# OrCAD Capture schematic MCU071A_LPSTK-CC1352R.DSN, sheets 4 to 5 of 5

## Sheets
4 4_Battery: size A3
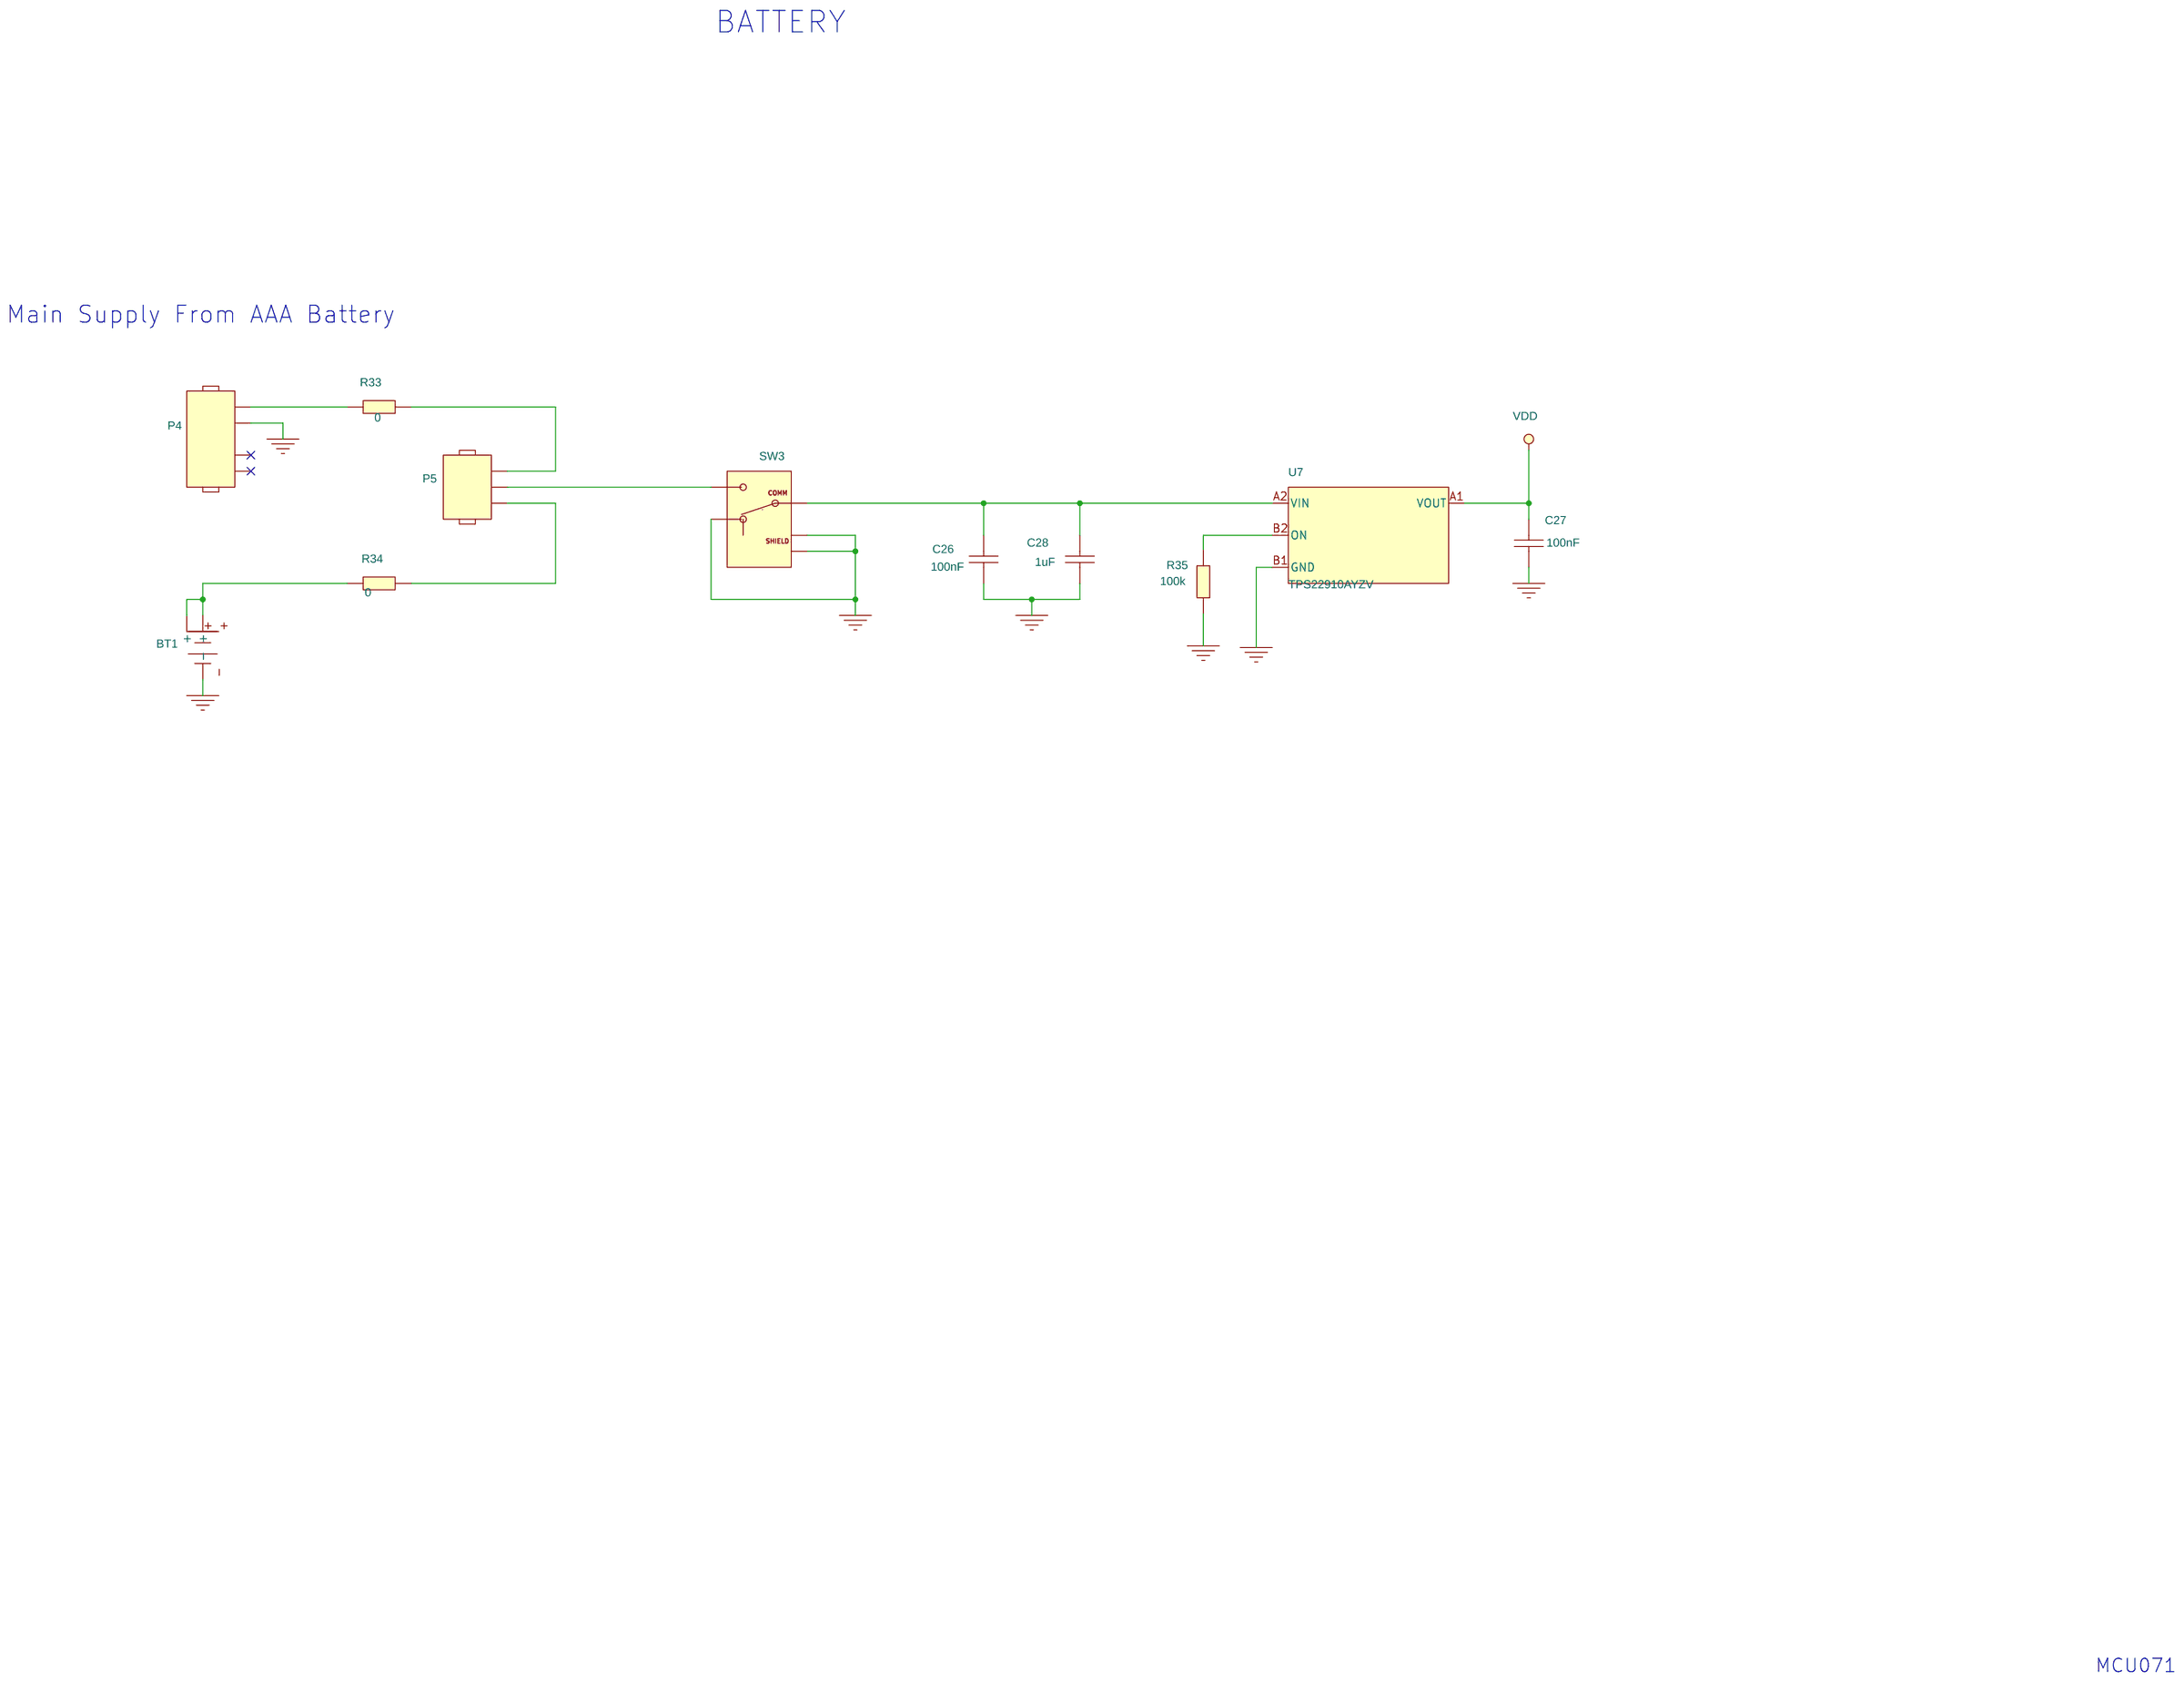
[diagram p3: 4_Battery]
5 5_Hardware: size A3
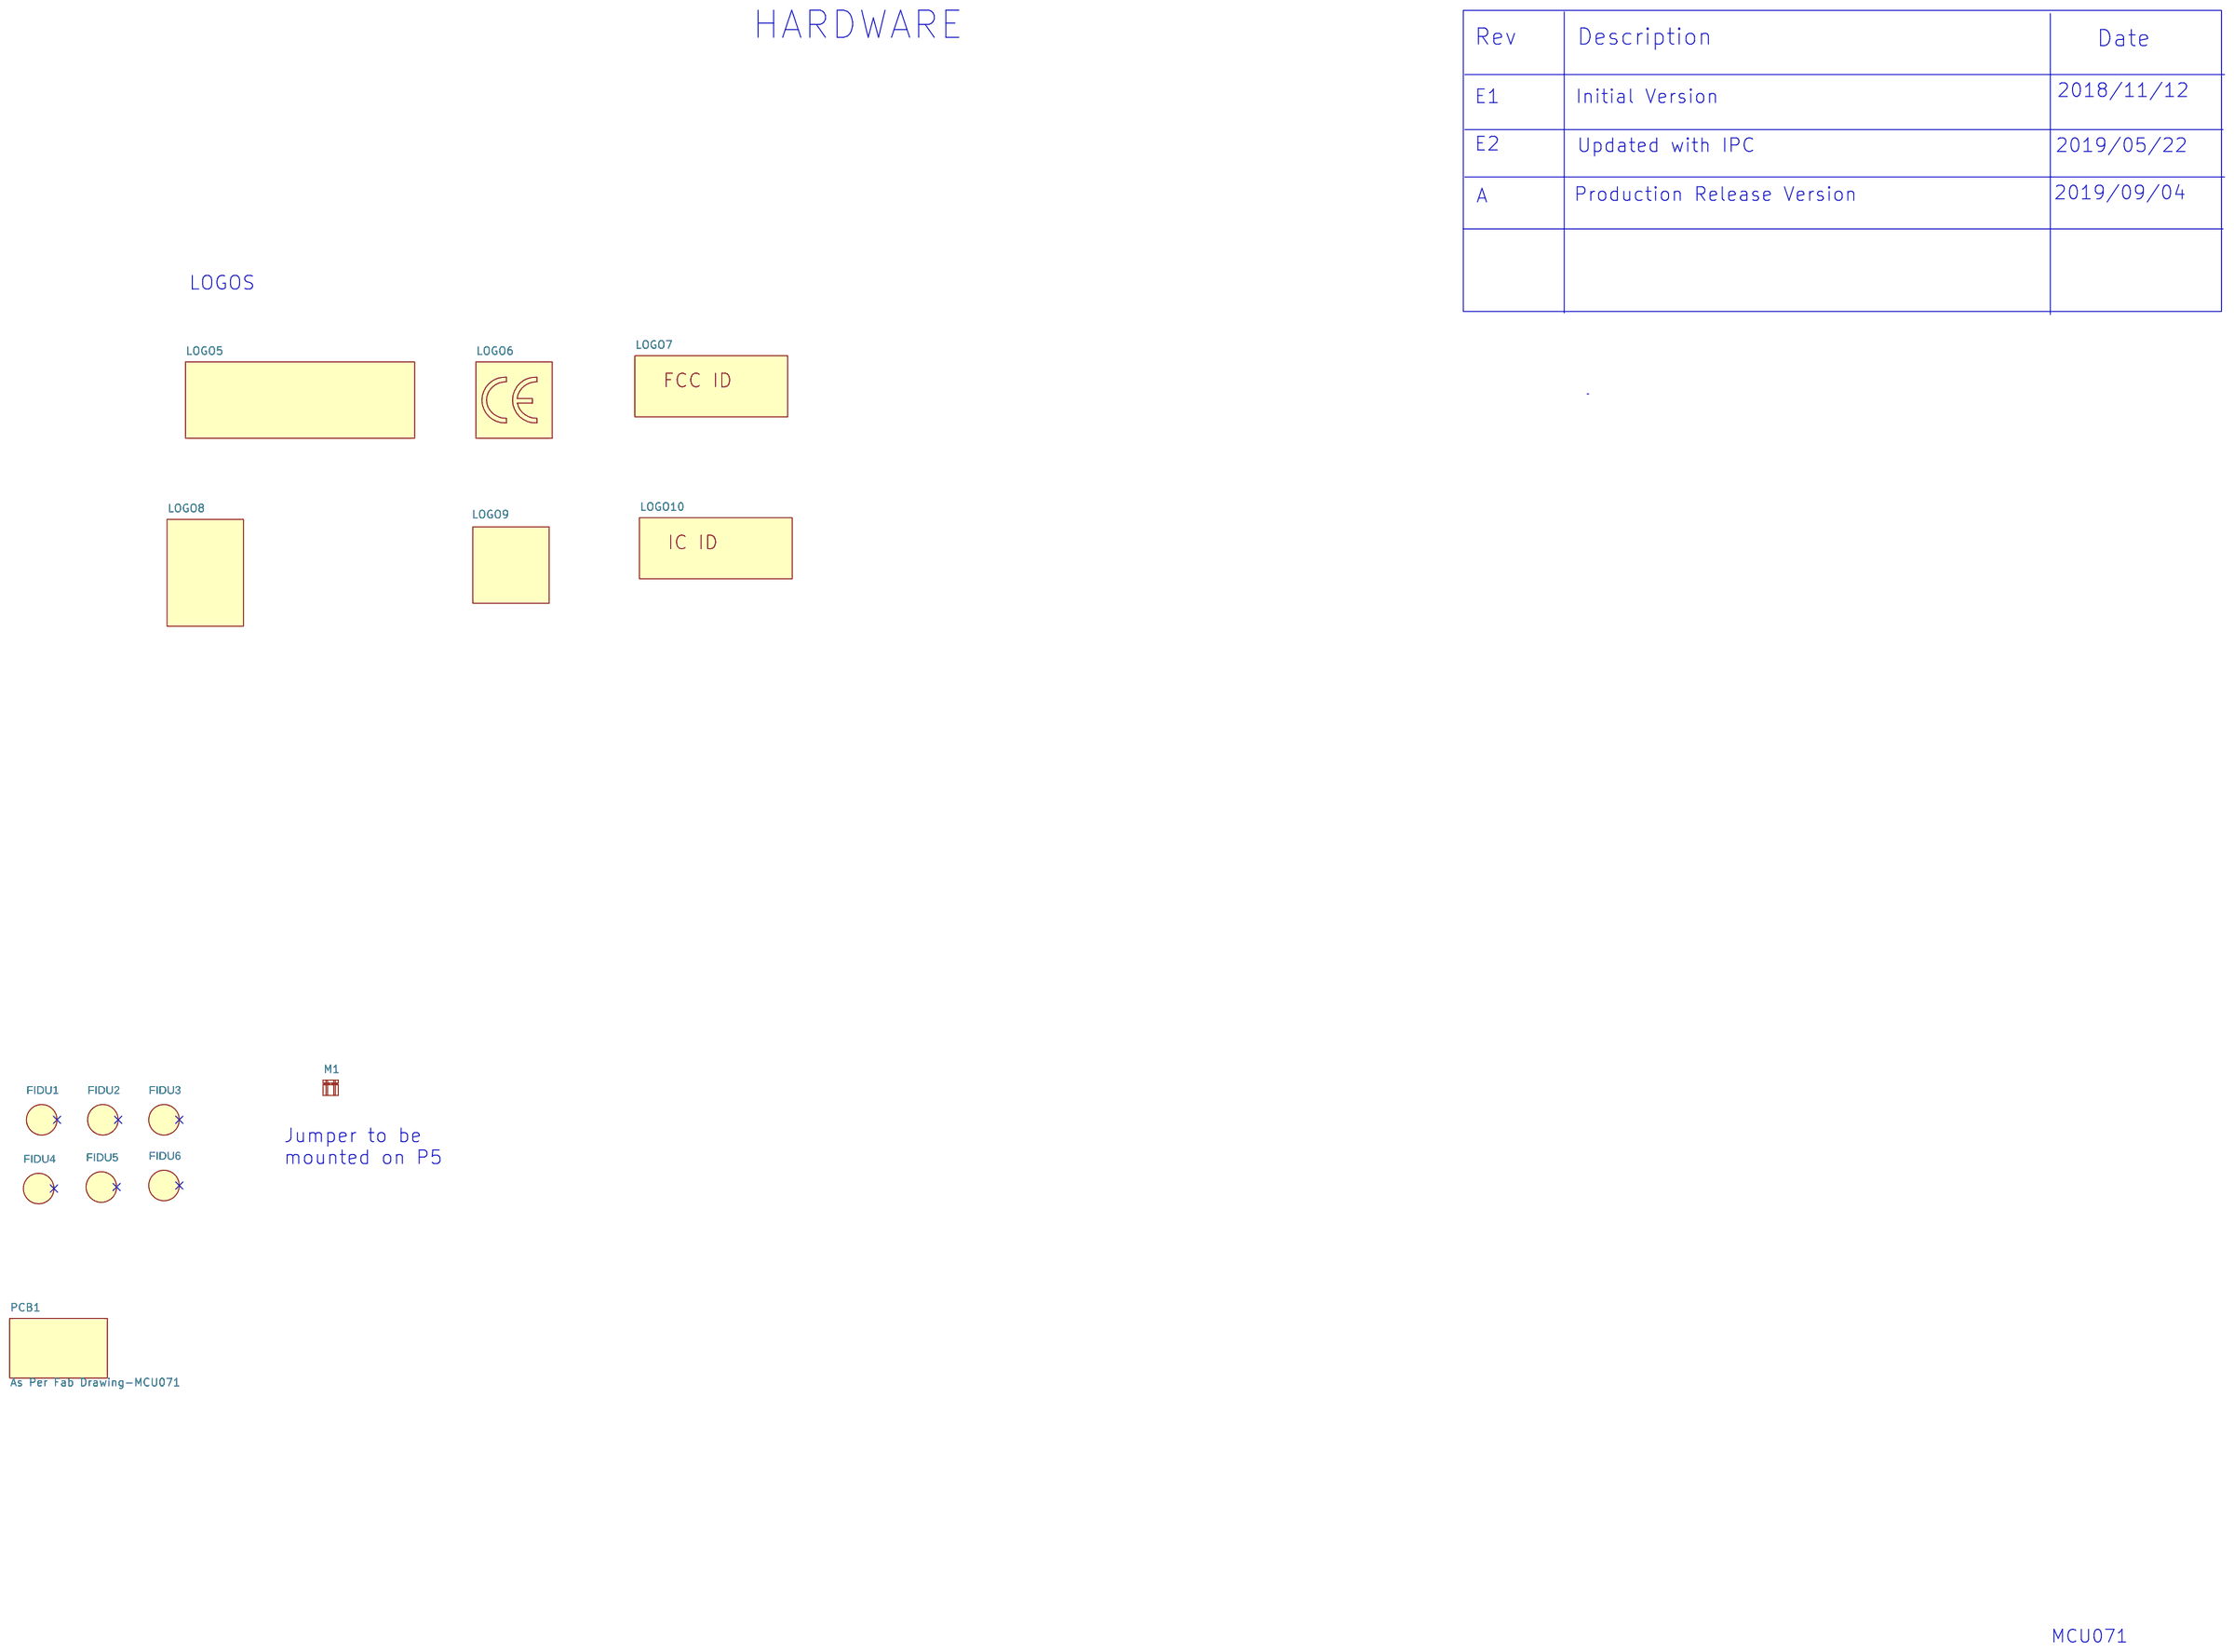
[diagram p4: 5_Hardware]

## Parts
sheet 4_Battery
BT1  BAT-HLD-001  [BAT_BATHLD001N]
C26  100nF  [CAPC1005X60A2N]
C27  100nF  [CAPC1005X60A2N]
C28  1uF  [CAPC1005X60A2N]
P4  CNT-1147H-02  [CNT_CNT1147H02_A2N]
P5  3220103S1210880  [HARWIN_M222010305_A2B]
R33  0  [RESC1005X40A2N]
R34  0  [RESC1005X40B2N]
R35  100k  [RESC0603X35B2N]
SW3  SH-12D01-VGX-H  [SW_SK12D01AVG_A2B]
U7  TPS22910AYZV  [BGAFC4C50P89X89X50]
sheet 5_Hardware
FIDU1  FIDU_1.27mm  [FID127X142]
FIDU2  FIDU_1.27mm  [FID127X142]
FIDU3  FIDU_1.27mm  [FID127X142]
FIDU4  FIDU_1.27mm  [FID127X142]
FIDU5  FIDU_1.27mm  [FID127X142]
FIDU6  FIDU_1.27mm  [FID127X142]
LOGO5  TI_LOGO  [TI_LOGO_1]
LOGO6  CE_Logo  [CE_MARKING]
LOGO7  FCC ID: Z64-LPSTK1352R  [LABEL_FOR_EVALUATION_ONLY]
LOGO8  TRASH_7mm  [TRASH_7MM]
LOGO9  ESD_Logo_5x5mm  [ESD_LABEL_5x5]
LOGO10  IC ID: 451I-LPSTKCC1352R  [LABEL_FOR_EVALUATION_ONLY]
M1  MJ-6B2.0X4.5  [SAMTEC_SNT100BKG]
PCB1  As Per Fab Drawing-MCU071  [TI_MCUxx]

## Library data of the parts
BT1 = BATT_3PINS: BATTERY, HOLDER, CR2032 AND CR2025 BATTERIES, SMD; ALT_SYMBOLS: BAT_BATHLD001L,BAT_BATHLD001M,BAT_BATHLD001AL,BAT_BATHLD001AM; Additional Datasheet URL: https://linxtechnologies.com/wp/wp-content/uploads/bat-hld-001.pdf; Budgetary Price: 0.2196 USD; Country of Origin: Missing Info; Datasheet URL: http://www.linxtechnologies.com/resources/documents/battery_holder_overview_guide.pdf; FPLIST: BAT_BATHLD001N,BAT_BATHLD001AN; Lead Time: 8; Mass: N/A; Maximum Operating Temperature: N/A; Minimum Operating Temperature: N/A; NOTEfied URL: https://notefied-dynamic-precision.com/NOTEfiedWebInterface/part/show?partNumber=10-00027; Packing Size: 100; Packing Type: Bulk; Part Number: 10-00027; Part Type: Battery|HOLDER; REACH/SVHC Compliance: Compliant; REACH/SVHC Details: SVHC List Version Jun 20, 2016; REACH/SVHC Source: REACH Declaration; REACH/SVHC Status: Unaffected; ROHS: Compliant; Revision: R013; Status: Released; Texas Part Status: Under Review; Type: Battery; Vendor: LINX; Vendor Part Status: Active
C26 C27 = CAPACITOR: CAPACITOR, CERAMIC X5R, 100nF, 10V, -10%+/10%, -55DEGC /+85DEGC, 0402, SMD; ALT_SYMBOLS: CAPC1005X60A2L,CAPC1005X60A2M; Additional Datasheet URL: http://www.avx.com/products/ceramic-capacitors/surface-mount/x5r-dielectric/; Budgetary Price: 0.004 EUR; Country of Origin: China,Czech Republic,El Salvador,Japan,Malaysia,United Kingdom; Datasheet URL: http://datasheets.avx.com/cx5r.pdf; Dielectric Type: X5R; Lead Time: 11; Mass: 0.001g; Maximum Operating Temperature: +85DEGC; Maximum Tolerance: +10%; Minimum Operating Temperature: -55DEGC; Minimum Tolerance: -10%; Mounting Type: SMD; NOTEfied URL: https://notefied-dynamic-precision.com/NOTEfiedWebInterface/part/show?partNumber=02-04065; PCB Package: 0402; Packing Size: 10000; Packing Type: Tape & Reel; Part Number: 02-04065; Part Type: Capacitor|CERAMIC|0402|STANDARD; ROHS: Compliant; Rated Voltage: 10V; Revision: R008; Status: Released; Type: Capacitor; Vendor: AVX; Vendor Part Number: 0402ZD104KAT2A; Vendor Part Status: Active
C28 = CAPACITOR: CAPACITOR, CERAMIC X5R, 1uF, 16V, -20%/+20%, -55DEGC/+85DEGC, 0402, SMD; ALT_SYMBOLS: CAPC1005X60A2L,CAPC1005X60A2M; Additional Datasheet URL: http://www.avx.com/products/ceramic-capacitors/surface-mount/x5r-dielectric/; Budgetary Price: 0.119 EUR; Country of Origin: United States; Datasheet URL: http://datasheets.avx.com/cx5r.pdf; Dielectric Type: X5R; Lead Time: 8; Mass: 0.001g; Maximum Operating Temperature: +85DEGC; Maximum Tolerance: +20%; Minimum Operating Temperature: -55DEGC; Minimum Tolerance: -20%; Mounting Type: SMD; NOTEfied URL: https://notefied-dynamic-precision.com/NOTEfiedWebInterface/part/show?partNumber=02-05023; PCB Package: 0402; Packing Size: 10000; Packing Type: Tape & Reel; Part Number: 02-05023; Part Type: Capacitor|CERAMIC|0402|STANDARD; ROHS: Compliant; Rated Voltage: 16V; Revision: R018; Status: Released; Type: Capacitor; Vendor: AVX; Vendor Part Number: 0402YD105MAT2A; Vendor Part Status: Active
P4 = CONN_HEADER_2_P_2MH_V1: CONNECTOR, HEADER, SHROUDED, MALE, RIGHT ANGLE, 1 ROW(S), 2 PINS, PITCH 1.25mm, SMD; ALT_SYMBOLS: CNT_CNT1147H02_A2L,CNT_CNT1147H02_A2M; Additional Datasheet URL: N/A; Datasheet URL: https://yccntcon.en.ec21.com/; Maximum Operating Temperature: +85DEGC; Minimum Operating Temperature: -40DEGC; Mounting Type: SMD; NOTEfied URL: https://notefied-dynamic-precision.com/NOTEfiedWebInterface/part/show?partNumber=06-07394; Number of Positions: 2; Number of Rows: 1; Packing Size: 2000; Packing Type: Tape & Reel; Part Number: 06-07394; Part Type: Connector|HEADER|SHROUDED; Pitch: 1.25mm; REACH/SVHC Compliance: Missing Info; REACH/SVHC Source: N/A; REACH/SVHC Status: Missing Info; ROHS: Compliant; Rated Current: 1A; Rated Voltage: 250V; Revision: R002; Status: Released; Texas Part Status: Under Review; Type: Connector; Vendor: CNT CONNECTORS; Vendor Part Status: Unconfirmed
P5 = CONN_HEADER_3_P_S: CONNECTOR, HEADER, MALE, STRAIGHT, 1 ROW, 3 PINS, PITCH 2mm, PTH; ALT_SYMBOLS: HARWIN_M222010305_A2A,HARWIN_M222010305_A2C; Additional Datasheet URL: https://cdn.harwin.com/pdfs/M22-201.pdf; Budgetary Price: 0.1066 USD; Country of Origin: Taiwan; Datasheet URL: https://cdn.harwin.com/pdfs/C018XX_M22_Series_Connectors.pdf; Mass: 0.071g; Maximum Operating Temperature: +105DEGC; Minimum Operating Temperature: -40DEGC; Mounting Type: PTH; NOTEfied URL: https://notefied-dynamic-precision.com/NOTEfiedWebInterface/part/show?partNumber=06-07362; Number of Positions: 3; Number of Rows: 1; Packing Size: 1000; Packing Type: Bulk; Part Number: 06-07362; Part Type: Connector|HEADER|STANDARD; Pitch: 2mm; REACH/SVHC Details: SVHC List Version; ROHS: Compliant; Rated Current: 2A; Rated Voltage: 650V; Revision: R003; Status: Released; Type: Connector; Vendor: LYCONN; Vendor Part Status: Active
R33 = RESISTOR: RESISTOR, THICK FILM, 0, 0.063W, 50V, -55DEGC/+155DEGC, 0402, SMD; ALT_SYMBOLS: RESC1005X40A2L,RESC1005X40A2M; Additional Datasheet URL: N/A; Budgetary Price: 0.00244 USD; Country of Origin: Missing Info; Datasheet URL: N/A; Mass: N/A; Maximum Operating Temperature: +155DEGC; Maximum Temperature Coefficient: +200PPM/DEGC; Maximum Tolerance: N/A; Minimum Operating Temperature: -55DEGC; Minimum Temperature Coeficient: -200PPM/DEGC; Minimum Tolerance: N/A; Mounting Type: SMD; NOTEfied URL: https://notefied-dynamic-precision.com/NOTEfiedWebInterface/part/show?partNumber=01-11587; PCB Package: 0402; Packing Size: 10000; Packing Type: Tape & Reel; Part Number: 01-11587; Part Type: Resistor|0402|JUMPER; ROHS: Compliant; Rated Current: N/A; Rated Power: 0.063W; Rated Voltage: 50V; Resistor Type: THICK FILM; Revision: R014; Status: Released; Type: Resistor; Vendor: Yageo; Vendor Part Number: RC0402JR-070RL; Vendor Part Status: Active
R34 = RESISTOR: RESISTOR, THICK FILM, 0, 0.063W, 50V, -55DEGC/+155DEGC,0402, SMD; Additional Datasheet URL: N/A; Country of Origin: Missing Info; Datasheet URL: N/A; Exclusive for Customers: TEXAS INSTRUMENTS NORWAY; Maximum Operating Temperature: N/A; Maximum Temperature Coefficient: N/A; Maximum Tolerance: N/A; Minimum Operating Temperature: N/A; Minimum Temperature Coeficient: N/A; Minimum Tolerance: N/A; Mounting Type: SMD; NOTEfied URL: https://notefied-dynamic-precision.com/NOTEfiedWebInterface/part/show?partNumber=01-22339; Notes: Standard item: Duplicate Reason: custom footprint for TEXAS INSTRUMENTS NORWAY.; PCB Package: 0402; Part Number: 01-22339; Part Type: Resistor|0402|STANDARD; ROHS: Compliant; Rated Current: N/A; Rated Power: N/A; Rated Voltage: N/A; Resistance: N/A; Resistor Type: THICK FILM; Revision: R012; Status: Released; Texas Part Status: Under Review; Type: Resistor; Vendor: Yageo; Vendor Part Number: RC0402JR-070RL; Vendor Part Status: Active
R35 = RESISTOR: RESISTOR, THICK FILM, 100k, -5%/+5%, 0.05W, 30V, -55DEGC/+155DEGC, 0201, SMD; ALT_SYMBOLS: RESC0603X35B2L,RESC0603X35B2M; Additional Datasheet URL: N/A; AutoDoc File: https://notefied-dynamic-precision.com/DB/Apps/Desktop/Item/Object.aspx?id=59027; BU Name: DYNAMIC PRECISION GDANSK; Budget Currency: USD; Budget Price: 0.0041; Budgetary Price: 0.0041 USD; Country of Origin: Taiwan; Datasheet URL: http://www.vishay.com/docs/20052/crcw0201e3.pdf; Datasheet URL 1: http://www.vishay.com/docs/20052/crcw0201e3.pdf; Datasheet URL 2: N/A; Definied Quality: MILITARY; Lead Time: 7; LifeCycle Status: ACTIVE; MPN: RESISTOR_0201_100k_+/-5%_30V_0.05W_M_+/-200ppm; MPN Status: ACTIVE; Manufacturer: MANUFACTURER SELECTION; Mass: 0.00017g; Max Oper Temp: +155DEGC; Max TC: +200PPM/DEGC; Max Tol: +5%; Maximum Operating Temperature: +155DEGC; Maximum Temperature Coefficient: +200PPM/DEGC; Maximum Tolerance: +5%; Min Oper Temp: -55DEGC; Min TC: -200PPM/DEGC; Min Tol: -5%; Minimum Operating Temperature: -55DEGC; Minimum Temperature Coeficient: -200PPM/DEGC; Minimum Tolerance: -5%; Mounting Type: SMD; NOTE Status: PREFERRED; NOTEfied URL: https://notefied-dynamic-precision.com/NOTEfiedWebInterface/part/show?partNumber=01-04220; Old Footprint: RESC0603X35N,0201; PCB Package: 0201; Packing Size: 10000; Packing Type: Tape & Reel; Part Number: 01-04220; Part Type: Resistor|0201|STANDARD; REACH/SVHC Compliance: Compliant; REACH/SVHC Details: SVHC List Version Dec 17, 2015; REACH/SVHC Source: Material Declaration; REACH/SVHC Status: Unaffected; ROHS: Exempt; Rated Current: N/A; Rated Power: 0.05W; Rated Voltage: 30V; Resistor Type: THICK FILM; Revision: R005; RoHS Status: ROHS_COMPLIANT; Rtd Current: N/A; Rtd Power: 0.05W; Rtd Voltage: 30V; Status: Released; Type: Resistor; Vendor: VISHAY; Vendor Part Number: CRCW0201100KJNED; Vendor Part Status: Active; Weight: 0.00017g
SW3 = SWITCH_SLIDE_3PIN_2MH: SWITCH, SLIDE, 2 POSITIONS, RIGHT ANGLE, SPDT, 0.3A@4VDC, PTH; ALT_SYMBOLS: SW_SK12D01AVG_A2A,SW_SK12D01AVG_A2C; Additional Datasheet URL: N/A; Datasheet URL: https://www.ckswitches.com/products/switches/product-details/Slide/SK/; Maximum Operating Temperature: +70DEGC; Minimum Operating Temperature: -20DEGC; Mounting Type: PTH; NOTEfied URL: https://notefied-dynamic-precision.com/NOTEfiedWebInterface/part/show?partNumber=08-00492; Part Number: 08-00492; Part Type: Switch|SLIDE; REACH/SVHC Compliance: Compliant; REACH/SVHC Details: SVHC List Version Jun 27, 2018; REACH/SVHC Source: REACH Declaration; REACH/SVHC Status: Unaffected; ROHS: Compliant; Rated Current: 0.3A; Rated Voltage: 4VDC; Revision: R002; Status: Released; Texas Part Status: Under Review; Type: Switch; Vendor: Chi Fung Electronics Co Ltd; Vendor Part Status: Active
U7 = IC_PM_TPS22910A_DSBGA4: IC, ANALOG, LOW ON-RESISTANCE LOAD SWITCH WITH CONTROLLED TURN-ON, ENABLE:ACTIVE LOW, 1.4V TO 5.5V, DSBGA4, SMD; Additional Datasheet URL: http://www.ti.com/litv/pdf/mxbg052b; AutoDoc File: http://notefied-dynamic-precision.com/DB/Apps/Desktop/Item/Object.aspx?id=97180; Budget Currency: USD; Budget Price: 0.24; Budgetary Price: 0.19 USD; Country of Origin: Missing Info; Datasheet URL: http://www.ti.com/lit/ds/symlink/tps22910a.pdf; Datasheet URL 1: http://www.ti.com/litv/pdf/mxbg052b; Datasheet URL 2: http://www.ti.com/lit/ds/symlink/tps22910a.pdf; Lead Time: 8; LifeCycle Status: ACTIVE; MPN: TPS22910AYZVR; MPN Status: ACTIVE; MSL: 1; Manufacturer: TEXAS INSTRUMENTS; Mass: 0.001g; Max Oper Temp: +85DEGC; Maximum Operating Temperature: +85DEGC; Min Oper Temp: -40DEGC; Minimum Operating Temperature: -40DEGC; Mounting Type: SMD; NOTE Status: PREFERRED; NOTEfied URL: https://notefied-dynamic-precision.com/NOTEfiedWebInterface/part/show?partNumber=18-29653; PCB Package: DSBGA4; Packing Size: 3000; Packing Type: Tape & Reel; Part Number: 18-29653; Part Type: IC|ANALOG|PM|SWITCH; ROHS: Compliant; Rated Current: 2A; Rated Voltage: 1.4V TO 5.5V; Revision: R016; RoHS Status: ROHS_COMPLIANT; Rtd Current: 2A; Rtd Voltage: 1.4V TO 5.5V; Status: Released; Texas Part Status: Under Review; Type: IC; Vendor: TEXAS INSTRUMENTS; Vendor Part Number: TPS22910AYZVR; Vendor Part Status: Active; WEIGHT: 0.001029761g
FIDU1-FIDU6 = FIDMARK: NON COMPONENT, FIDUCIAL MARK, ROUND 1.27MM, SMD; Additional Datasheet URL: N/A; CLASS: IO; Country of Origin: Missing Info; Datasheet URL: N/A; Mass: N/A; Mounting Type: SMD; NOTEfied URL: https://notefied-dynamic-precision.com/NOTEfiedWebInterface/part/show?partNumber=19-00300; Packing Size: N/A; Packing Type: Missing Info; Part Number: 19-00300; Part Type: Non Component|FIDUCIAL; ROHS: Missing Info; Revision: R011; Status: Released; Texas Part Status: Under Review; Type: Non Component; Vendor: NON_COMPONENT; Vendor Part Number: FIDUCIAL_1.27mm; Vendor Part Status: Active
LOGO5 = TI_LOGO_V1: NON COMPONENT, LOGO, TEXAS INSTRUMENTS LOGO; Additional Datasheet URL: N/A; AutoDoc File: https://notefied-dynamic-precision.com/DB/Apps/Desktop/Item/Object.aspx?id=87770; BU Name: TEXAS INSTRUMENTS NORWAY; Country of Origin: Missing Info; Datasheet URL: N/A; Exclusive for Customers: TEXAS INSTRUMENTS NORWAY; Mass: N/A; Mounting Type: Not Apply; NOTEfied URL: https://notefied-dynamic-precision.com/NOTEfiedWebInterface/part/show?partNumber=19-00350; Notes: Custom Item; Packing Size: N/A; Packing Type: Missing Info; Part Number: 19-00350; Part Type: Non Component|LABEL; ROHS: Missing Info; Revision: R013; Status: Released; Texas Part Status: Under Review; Type: Non Component; Vendor: NON_COMPONENT; Vendor Part Status: Active
LOGO6 = CE_LABEL_V1: NON COMPONENT, LOGO, CE; Additional Datasheet URL: N/A; Country of Origin: Missing Info; Datasheet URL: http://www.ce-marking.com/CE-marking-logo.html; Mass: N/A; Mounting Type: Not Apply; NOTEfied URL: https://notefied-dynamic-precision.com/NOTEfiedWebInterface/part/show?partNumber=19-00351; Packing Size: N/A; Packing Type: Missing Info; Part Number: 19-00351; Part Type: Non Component|LABEL; ROHS: Missing Info; Revision: R014; Status: Released; Texas Part Status: Under Review; Type: Non Component; Vendor: NON_COMPONENT; Vendor Part Number: CE_LABEL; Vendor Part Status: Active
LOGO7 = LABEL_FOR_EVALUATOIN_ONLY_0: NON COMPONENT, LOGO, FCC ID: Z64-LPSTK1352R; AutoDoc File: https://notefied-dynamic-precision.com/DB/Apps/Desktop/Item/Object.aspx?id=115268; BU Name: TEXAS INSTRUMENTS NORWAY; Part Number: 19-00830; Part Type: NON_COMPONENT\LABEL; Revision: R002
LOGO8 = TRASH_V2: NON COMPONENT, LOGO, TRASH 7mm; Additional Datasheet URL: N/A; Country of Origin: Missing Info; Datasheet URL: N/A; Mass: N/A; Mounting Type: Not Apply; NOTEfied URL: https://notefied-dynamic-precision.com/NOTEfiedWebInterface/part/show?partNumber=19-01044; Packing Size: N/A; Packing Type: Missing Info; Part Number: 19-01044; Part Type: Non Component|LABEL; ROHS: Missing Info; Revision: R007; Status: Released; Texas Part Status: Under Review; Type: Non Component; Vendor: NON_COMPONENT; Vendor Part Status: Active
LOGO9 = ESD_LABEL: NON COMPONENT, LOGO, ESD, 5 X 5 mm; Additional Datasheet URL: N/A; Country of Origin: Missing Info; Datasheet URL: N/A; Mass: N/A; Maximum Operating Temperature: N/A; Minimum Operating Temperature: N/A; Mounting Type: Not Apply; NOTEfied URL: https://notefied-dynamic-precision.com/NOTEfiedWebInterface/part/show?partNumber=19-00471; Packing Size: N/A; Packing Type: Missing Info; Part Number: 19-00471; Part Type: Non Component|LABEL; ROHS: Not Applicable; Revision: R007; Status: Released; Type: Non Component; Vendor: NON_COMPONENT; Vendor Part Number: ESD_LABEL_5x5mm; Vendor Part Status: Active
LOGO10 = LABEL_FOR_EVALUATOIN_ONLY_1: NON COMPONENT, LOGO, IC ID: 451I-LPSTKCC1352R; AutoDoc File: https://notefied-dynamic-precision.com/DB/Apps/Desktop/Item/Object.aspx?id=115268; BU Name: TEXAS INSTRUMENTS NORWAY; Part Number: 19-00830; Part Type: NON_COMPONENT\LABEL; Revision: R002
M1 = MECH_SHUNT_JUMPER_V1: MECHANIC, SHUNT, CURRENT RATING 4.3A PER PIN, 2.54 X 5.08 X 6.1mm, BLACK; Additional Datasheet URL: http://suddendocs.samtec.com/prints/snt-100-xx-x-x-mkt.pdf; Budgetary Price: 0.14525 USD; Country of Origin: China,Costa Rica,Malaysia,Singapore,United States; Datasheet URL: http://suddendocs.samtec.com/catalog_english/snt.pdf; Lead Time: 3; Mass: 0.11724g; Maximum Operating Temperature: +125DEGC; Minimum Operating Temperature: -55DEGC; Mounting Type: Not Apply; NOTEfied URL: https://notefied-dynamic-precision.com/NOTEfiedWebInterface/part/show?partNumber=19-00498; Packing Size: 1; Packing Type: Bulk; Part Number: 19-00498; Part Type: Mechanic|SHUNT; REACH/SVHC Compliance: Compliant; REACH/SVHC Details: SVHC List Version Dec 17, 2015; REACH/SVHC Source: Material Declaration; REACH/SVHC Status: Unaffected; ROHS: Compliant; Rated Current: 4.3A; Revision: R015; Status: Released; Texas Part Status: Under Review; Type: Mechanic; Vendor: SHENZHENLYCN ELECTRONICS; Vendor Part Status: Active
PCB1 = PCB_V2: NON COMPONENT, PCB, TEXAS INSTRUMENTS; Additional Datasheet URL: N/A; Datasheet URL: N/A; Exclusive for Customers: TEXAS INSTRUMENTS NORWAY; Mounting Type: Not Apply; NOTEfied URL: https://notefied-dynamic-precision.com/NOTEfiedWebInterface/part/show?partNumber=19-00925; Notes: Custom PCB outline.; Packing Type: Missing Info; Part Number: 19-00925; Part Type: Non Component|PCB; ROHS: Complies; Revision: R003; Status: Released; Texas Part Status: Under Review; Type: Non Component; Vendor: Lierda; Vendor Part Number: MCU071; Vendor Part Status: Active

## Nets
GND: BT1.3(-) C26.2 C27.2 C28.2 P4.2 R35.1 SW3.1 SW3.M1 SW3.M2 U7.B1(GND) ; also on sheet 1 2 3
VDD: C27.1 U7.A1(VOUT) ; also on sheet 1 2 3
N2848828: R35.2 U7.B2(ON)
N2848936: P5.3 R34.1
N3065409: BT1.1(+) BT1.2(+) R34.2
N3065598: P5.2 SW3.3
N3066069: P4.1 R33.2
N3066097: P5.1 R33.1
N3066149: C26.1 C28.1 SW3.2 U7.A2(VIN)

Not connected (* = marked no-connect by the designer): FIDU1 1*; FIDU2 1*; FIDU3 1*; FIDU4 1*; FIDU5 1*; FIDU6 1*; P4 M1* M2*

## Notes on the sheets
sheet 4
- BATTERY
- Main Supply From AAA Battery
- MCU071
sheet 5
- HARDWARE
- Rev
- Description
- Date
- E1
- Initial Version
- 2018/11/12
- E2
- Updated with IPC
- 2019/05/22
- A
- Production Release Version
- 2019/09/04
- LOGOS
- Jumper to be
  mounted on P5
- MCU071
